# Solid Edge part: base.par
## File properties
Title: Base
Author: Robert a Rhodes jr
Template: Normal.par
Last saved by: CADCIM
Revision: 23
Application: Solid Edge
Accuracy: 0.99
Material: aluminum
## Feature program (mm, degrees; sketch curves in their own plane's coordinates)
sketch for "unnamed Protrusion 1" plane through (0, 0, 0) normal (0, 0, 1) x-axis (1, 0, 0)
  line (-85, 25) -> (-85, -25)
  arc centre (-80, -25) radius 5 from (-85, -25) to (-80, -30) ccw
  line (-80, -30) -> (80, -30)
  arc centre (80, -25) radius 5 from (85, -25) to (80, -30) cw
  line (85, -25) -> (85, 25)
  arc centre (80, 25) radius 5 from (80, 30) to (85, 25) cw
  line (80, 30) -> (-80, 30)
  arc centre (-80, 25) radius 5 from (-85, 25) to (-80, 30) cw
extrude "unnamed Protrusion 1" add finite 20 along +normal
sketch for "ExtrudedProtrusion_2" plane through (5, -12, 10) normal (0, -1, 0) x-axis (1, 0, 0)
  line (-50, 10) -> (-50, 50)
  arc centre (15, 50) radius 65 from (-50, 50) to (-20, 104.7723) cw
  line (-20, 104.7723) -> (-20, 144)
  arc centre (-17, 144) radius 3 from (-20, 144) to (-17, 147) cw
  line (-17, 147) -> (37, 147)
  arc centre (37, 144) radius 3 from (37, 147) to (40, 144) cw
  line (40, 144) -> (40, 75)
  line (40, 75) -> (-12, 75)
  line (-12, 28.959) -> (-12, 75)
  line (10, 10) -> (-12, 28.959)
  line (28, 35) -> (10, 10)
  line (40, 35) -> (28, 35)
  line (40, 35) -> (40, 10)
extrude "ExtrudedProtrusion_2" add  Plane_Distance = 18 mm
sketch for "unnamed Cutout 1" plane through (5, -12, 88.5) normal (0, -1, 0) x-axis (1, 0, 0)
  line (-20, -68.5) -> (-20, 4.7281)
  arc centre (-25, 4.7281) radius 5 from (-28.8, 7.9777) to (-20, 4.7281) cw
  arc centre (13, -27.7681) radius 55 from (-42, -27.7681) to (-28.8, 7.9777) cw
  line (-42, -68.5) -> (-42, -27.7681)
  line (-42, -68.5) -> (-20, -68.5)
extrude "unnamed Cutout 1" cut finite 10 along -normal
sketch for "ExtrudedCutout_2" plane through (5, 0, 0) normal (0, 0, -1) x-axis (1, 0, 0)
  line (-10, 1) -> (-10, -19)
  line (-10, -19) -> (30, -19)
  line (30, -19) -> (30, 1)
  line (30, 1) -> (-10, 1)
  dimension (linear) = 10
extrude "ExtrudedCutout_2" cut finite 147 along -normal
sketch for "ExtrudedProtrusion_3" plane through (25, 9, 157) normal (0, 0, 1) x-axis (1, 0, 0)
  circle centre (-10, 0) radius 15
  dimension (linear) = 10
extrude "ExtrudedProtrusion_3" add finite 18 along +normal
sketch for "Hole_1" plane through (25, 9, 175) normal (0, 0, 1) x-axis (1, 0, 0)
  hole centre (-10, 0) bore radius 10
hole "Hole_1" diameter 20 finite
sketch for "Hole_2" plane through (45, 9, 119.9119) normal (1, 0, 0) x-axis (0, 1, 0)
  hole centre (1, 20.0881) bore radius 4
  dimension (linear) = 1
hole "Hole_2" diameter 8 through
mirror "unnamed Mirror 1" of "unnamed Cutout 1" about plane through (5, 9, 88.7059) normal (0, -1, 0)
extrude "unnamed Cutout 2" cut finite 10
fillet "Round_1" radius 3
sketch for "Hole_3" plane through (0, 0, 20) normal (0, 0, 1) x-axis (1, 0, 0)
  hole centre (70, 0) bore radius 6.5
hole "Hole_3" diameter 13 through
sketch for "unnamed Hole 1" plane through (0, 0, 20) normal (0, 0, 1) x-axis (1, 0, 0)
  hole centre (-70, 0) bore radius 6.5
  dimension (linear) = 70
  dimension (linear) = 70
hole "unnamed Hole 1" through
pattern "unnamed Pattern 1" of "Hole_3", "unnamed Hole 1"
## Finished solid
Body 1: solid body, 61 faces, 164 edges, 100 vertices.
  Faces by surface: plane 37, cylinder 23, torus 1
  Edges by curve: line 114, circle 50
Bounding box of the edges (mm; curved faces can reach further): 170.000 x 60.000 x 175.000, from (-85, -30, 0) to (85, 30, 175).
Cylindrical faces by radius (mm): R3 x8, R4 x2, R5 x6, R6.5 x2, R10 x1, R15 x1, R55 x2, R65 x1
Toroidal faces (ring radius, tube radius in mm): R18 r3 x1
Planar faces by outward normal: +x 8, +y 4, +z 5, -x 7, -y 6, -z 4, oblique 3
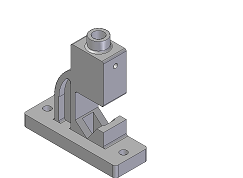
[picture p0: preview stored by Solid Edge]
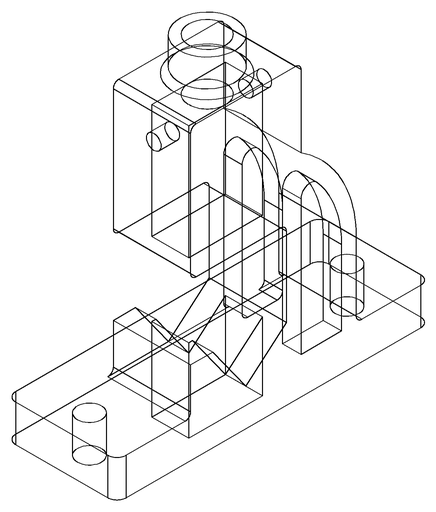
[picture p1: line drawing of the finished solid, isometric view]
